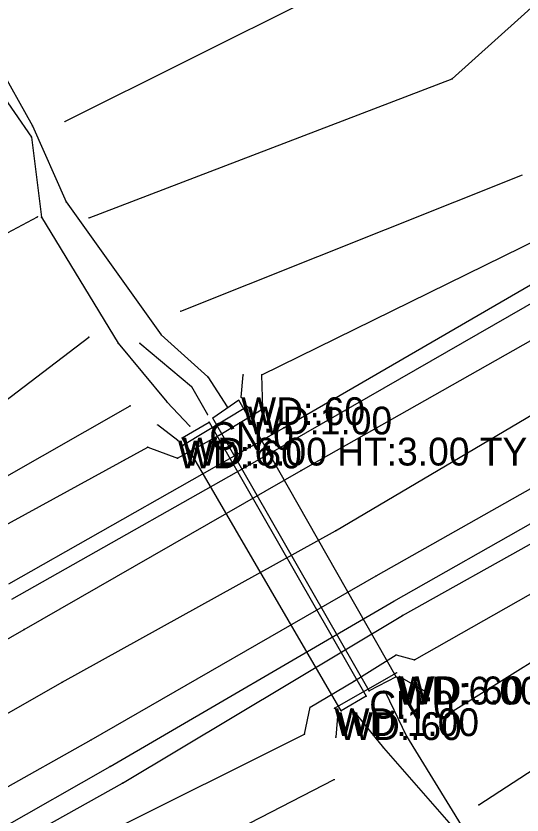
# Model space of a CAD drawing. Extents: x 1419505 to 1434054, y 1956910 to 1968644.
# Drawn here: x 1420049.5 to 1420140.6, y 1957211.1 to 1957354.8 of the extents above; entities that cross this region are included whole.
import ezdxf

# ---------------------------------------------------------------- set-up
doc = ezdxf.new("R2010")
doc.units = 0
for name, color, linetype in [('S_BREAKLINE', 7, 'Continuous'), ('S_CROSS_DRAIN', 7, 'Continuous'), ('S_CROSS_DRAIN_ANNOT', 7, 'Continuous'), ('S_DITCHLINE', 7, 'Continuous'), ('S_DRG_PT_SYM', 7, 'Continuous'), ('S_EDGE_PAVEMENT', 7, 'Continuous'), ('S_GRD_PT_SYM', 7, 'Continuous'), ('S_HEADWALL', 7, 'Continuous'), ('S_HEADWALL_ANNOT', 7, 'Continuous'), ('S_MSC_PT_SYM', 7, 'Continuous'), ('S_PAVEMENT_CROWN', 7, 'Continuous'), ('S_RDW_PT_SYM', 7, 'Continuous'), ('S_SHOULDER', 7, 'Continuous'), ('S_WALL', 7, 'Continuous'), ('S_WALL_ANNOT', 7, 'Continuous')]:
    doc.layers.add(name, color=color, linetype=linetype)

msp = doc.modelspace()

# ---------------------------------------------------------------- linework, layer by layer
at = {"layer": 'S_BREAKLINE'}
for p, q in [((1420127.9904, 1957343.5183), (1420164.2098, 1957376.2314)), ((1420058.3479, 1957335.8728), (1420113.5025, 1957363.3696)), ((1420062.6692, 1957318.5327), (1420127.9904, 1957343.5183)), ((1420079.1623, 1957301.7136), (1420140.6403, 1957326.2372)), ((1420007.4567, 1957294.0961), (1420053.3996, 1957318.7217)), ((1420093.7432, 1957290.3199), (1420146.6607, 1957316.3055)), ((1420097.7205, 1957280.7592), (1420147.7647, 1957309.7911)), ((1420034.2654, 1957275.5089), (1420062.6502, 1957297.0553)), ((1420071.8348, 1957295.9782), (1420081.0834, 1957288.1657)), ((1420093.9612, 1957284.1805), (1420093.7432, 1957290.3199)), ((1420081.0834, 1957288.1657), (1420083.9876, 1957283.1844)), ((1420037.8606, 1957266.3443), (1420070.0887, 1957284.7075)), ((1420086.1067, 1957279.4271), (1420093.9612, 1957284.1805)), ((1420048.2403, 1957252.7354), (1420097.7205, 1957280.7592)), ((1420078.5733, 1957275.3109), (1420086.1067, 1957279.4271)), ((1420042.4399, 1957260.4189), (1420073.2449, 1957277.283)), ((1420073.2449, 1957277.283), (1420078.5733, 1957275.3109)), ((1420121.211, 1957239.0335), (1420187.0263, 1957276.508)), ((1420119.0419, 1957247.0051), (1420167.564, 1957274.1688)), ((1420127.2204, 1957229.2889), (1420189.2894, 1957268.1244)), ((1420132.7968, 1957212.9439), (1420196.5619, 1957254.8196)), ((1420068.6666, 1957216.8621), (1420119.0419, 1957247.0051)), ((1420110.2393, 1957235.1233), (1420117.9418, 1957239.9706)), ((1420117.9418, 1957239.9706), (1420121.211, 1957239.0335)), ((1420102.4758, 1957230.514), (1420110.2393, 1957235.1233)), ((1420101.4407, 1957225.7017), (1420102.4758, 1957230.514)), ((1420063.9153, 1957206.9805), (1420101.4407, 1957225.7017)), ((1420071.8068, 1957199.561), (1420106.7861, 1957217.5232)), ((1420019.4294, 1957189.4423), (1420068.6666, 1957216.8621))]:
    msp.add_line(p, q, dxfattribs=at)
at = {"layer": 'S_CROSS_DRAIN'}
for p, q in [((1420089.64, 1957285.7056), (1420084.9237, 1957282.5193)), ((1420117.9348, 1957236.0053), (1420089.64, 1957285.7056)), ((1420113.0735, 1957233.4652), (1420084.9237, 1957282.5193)), ((1420079.4443, 1957278.9851), (1420084.2976, 1957281.7913)), ((1420084.2976, 1957281.7913), (1420112.5044, 1957232.5051)), ((1420108.0462, 1957229.8769), (1420079.4443, 1957278.9851)), ((1420117.9348, 1957236.0053), (1420113.0735, 1957233.4652)), ((1420112.5044, 1957232.5051), (1420108.0462, 1957229.8769))]:
    msp.add_line(p, q, dxfattribs=at)
at = {"layer": 'S_DITCHLINE'}
for p, q in [((1420042.2079, 1957353.3429), (1420052.5236, 1957335.0637)), ((1420039.4067, 1957351.6418), (1420052.3436, 1957333.0406)), ((1420052.5236, 1957335.0637), (1420058.565, 1957321.3969)), ((1420052.3436, 1957333.0406), (1420054.1217, 1957318.6297)), ((1420058.565, 1957321.3969), (1420075.6421, 1957297.5113)), ((1420054.1217, 1957318.6297), (1420067.9146, 1957295.9772)), ((1420075.6421, 1957297.5113), (1420084.0236, 1957289.9098)), ((1420067.9146, 1957295.9772), (1420076.6621, 1957285.4525)), ((1420084.0236, 1957289.9098), (1420087.5148, 1957284.5545)), ((1420076.6621, 1957285.4525), (1420080.8204, 1957281.0853)), ((1420115.9467, 1957233.2612), (1420119.8009, 1957225.3427)), ((1420109.9293, 1957230.256), (1420115.6606, 1957223.2085)), ((1420119.8009, 1957225.3427), (1420129.6166, 1957209.3256)), ((1420115.6606, 1957223.2085), (1420127.8044, 1957209.3356))]:
    msp.add_line(p, q, dxfattribs=at)
at = {"layer": 'S_DRG_PT_SYM'}
for points in [[(1420089.64, 1957285.7056), (1420089.64, 1957285.7556), (1420089.64, 1957285.7056), (1420089.59, 1957285.7056), (1420089.64, 1957285.7056), (1420089.64, 1957285.6556), (1420089.64, 1957285.7056), (1420089.69, 1957285.7056)], [(1420084.9237, 1957282.5193), (1420084.9237, 1957282.5693), (1420084.9237, 1957282.5193), (1420084.8737, 1957282.5193), (1420084.9237, 1957282.5193), (1420084.9237, 1957282.4693), (1420084.9237, 1957282.5193), (1420084.9737, 1957282.5193)], [(1420084.2976, 1957281.7913), (1420084.2976, 1957281.8413), (1420084.2976, 1957281.7913), (1420084.2476, 1957281.7913), (1420084.2976, 1957281.7913), (1420084.2976, 1957281.7413), (1420084.2976, 1957281.7913), (1420084.3476, 1957281.7913)], [(1420079.4443, 1957278.9851), (1420079.4443, 1957279.0351), (1420079.4443, 1957278.9851), (1420079.3943, 1957278.9851), (1420079.4443, 1957278.9851), (1420079.4443, 1957278.9351), (1420079.4443, 1957278.9851), (1420079.4943, 1957278.9851)], [(1420117.9348, 1957236.0053), (1420117.9348, 1957236.0553), (1420117.9348, 1957236.0053), (1420117.8848, 1957236.0053), (1420117.9348, 1957236.0053), (1420117.9348, 1957235.9553), (1420117.9348, 1957236.0053), (1420117.9848, 1957236.0053)], [(1420113.0735, 1957233.4652), (1420113.0735, 1957233.5152), (1420113.0735, 1957233.4652), (1420113.0235, 1957233.4652), (1420113.0735, 1957233.4652), (1420113.0735, 1957233.4152), (1420113.0735, 1957233.4652), (1420113.1235, 1957233.4652)], [(1420112.5044, 1957232.5051), (1420112.5044, 1957232.5551), (1420112.5044, 1957232.5051), (1420112.4544, 1957232.5051), (1420112.5044, 1957232.5051), (1420112.5044, 1957232.4551), (1420112.5044, 1957232.5051), (1420112.5544, 1957232.5051)], [(1420108.0462, 1957229.8769), (1420108.0462, 1957229.9269), (1420108.0462, 1957229.8769), (1420107.9962, 1957229.8769), (1420108.0462, 1957229.8769), (1420108.0462, 1957229.8269), (1420108.0462, 1957229.8769), (1420108.0962, 1957229.8769)]]:
    msp.add_lwpolyline(points, dxfattribs=at)
at = {"layer": 'S_EDGE_PAVEMENT'}
for p, q in [((1420100.8177, 1957273.1157), (1420152.421, 1957302.3016)), ((1420114.3446, 1957254.1415), (1420163.3257, 1957281.9013)), ((1420051.0225, 1957244.4839), (1420100.8177, 1957273.1157)), ((1420063.0773, 1957224.6846), (1420114.3446, 1957254.1415)), ((1420001.0552, 1957216.0471), (1420051.0225, 1957244.4839)), ((1420013.41, 1957196.7858), (1420063.0773, 1957224.6846))]:
    msp.add_line(p, q, dxfattribs=at)
at = {"layer": 'S_GRD_PT_SYM'}
for points in [[(1420127.9904, 1957343.5183), (1420127.9904, 1957343.5683), (1420127.9904, 1957343.5183), (1420127.9404, 1957343.5183), (1420127.9904, 1957343.5183), (1420127.9904, 1957343.4683), (1420127.9904, 1957343.5183), (1420128.0404, 1957343.5183)], [(1420058.3479, 1957335.8728), (1420058.3479, 1957335.9228), (1420058.3479, 1957335.8728), (1420058.2979, 1957335.8728), (1420058.3479, 1957335.8728), (1420058.3479, 1957335.8228), (1420058.3479, 1957335.8728), (1420058.3979, 1957335.8728)], [(1420052.5236, 1957335.0637), (1420052.5236, 1957335.1137), (1420052.5236, 1957335.0637), (1420052.4736, 1957335.0637), (1420052.5236, 1957335.0637), (1420052.5236, 1957335.0137), (1420052.5236, 1957335.0637), (1420052.5736, 1957335.0637)], [(1420052.3436, 1957333.0406), (1420052.3436, 1957333.0906), (1420052.3436, 1957333.0406), (1420052.2936, 1957333.0406), (1420052.3436, 1957333.0406), (1420052.3436, 1957332.9906), (1420052.3436, 1957333.0406), (1420052.3936, 1957333.0406)], [(1420058.565, 1957321.3969), (1420058.565, 1957321.4469), (1420058.565, 1957321.3969), (1420058.515, 1957321.3969), (1420058.565, 1957321.3969), (1420058.565, 1957321.3469), (1420058.565, 1957321.3969), (1420058.615, 1957321.3969)], [(1420053.3996, 1957318.7217), (1420053.3996, 1957318.7717), (1420053.3996, 1957318.7217), (1420053.3496, 1957318.7217), (1420053.3996, 1957318.7217), (1420053.3996, 1957318.6717), (1420053.3996, 1957318.7217), (1420053.4496, 1957318.7217)], [(1420054.1217, 1957318.6297), (1420054.1217, 1957318.6797), (1420054.1217, 1957318.6297), (1420054.0717, 1957318.6297), (1420054.1217, 1957318.6297), (1420054.1217, 1957318.5797), (1420054.1217, 1957318.6297), (1420054.1717, 1957318.6297)], [(1420062.6692, 1957318.5327), (1420062.6692, 1957318.5827), (1420062.6692, 1957318.5327), (1420062.6192, 1957318.5327), (1420062.6692, 1957318.5327), (1420062.6692, 1957318.4827), (1420062.6692, 1957318.5327), (1420062.7192, 1957318.5327)], [(1420079.1623, 1957301.7136), (1420079.1623, 1957301.7636), (1420079.1623, 1957301.7136), (1420079.1123, 1957301.7136), (1420079.1623, 1957301.7136), (1420079.1623, 1957301.6636), (1420079.1623, 1957301.7136), (1420079.2123, 1957301.7136)], [(1420062.6502, 1957297.0553), (1420062.6502, 1957297.1053), (1420062.6502, 1957297.0553), (1420062.6002, 1957297.0553), (1420062.6502, 1957297.0553), (1420062.6502, 1957297.0053), (1420062.6502, 1957297.0553), (1420062.7002, 1957297.0553)], [(1420075.6421, 1957297.5113), (1420075.6421, 1957297.5613), (1420075.6421, 1957297.5113), (1420075.5921, 1957297.5113), (1420075.6421, 1957297.5113), (1420075.6421, 1957297.4613), (1420075.6421, 1957297.5113), (1420075.6921, 1957297.5113)], [(1420067.9146, 1957295.9772), (1420067.9146, 1957296.0272), (1420067.9146, 1957295.9772), (1420067.8646, 1957295.9772), (1420067.9146, 1957295.9772), (1420067.9146, 1957295.9272), (1420067.9146, 1957295.9772), (1420067.9646, 1957295.9772)], [(1420071.8348, 1957295.9782), (1420071.8348, 1957296.0282), (1420071.8348, 1957295.9782), (1420071.7848, 1957295.9782), (1420071.8348, 1957295.9782), (1420071.8348, 1957295.9282), (1420071.8348, 1957295.9782), (1420071.8848, 1957295.9782)], [(1420084.0236, 1957289.9098), (1420084.0236, 1957289.9598), (1420084.0236, 1957289.9098), (1420083.9736, 1957289.9098), (1420084.0236, 1957289.9098), (1420084.0236, 1957289.8598), (1420084.0236, 1957289.9098), (1420084.0736, 1957289.9098)], [(1420093.7432, 1957290.3199), (1420093.7432, 1957290.3699), (1420093.7432, 1957290.3199), (1420093.6932, 1957290.3199), (1420093.7432, 1957290.3199), (1420093.7432, 1957290.2699), (1420093.7432, 1957290.3199), (1420093.7932, 1957290.3199)], [(1420081.0834, 1957288.1657), (1420081.0834, 1957288.2157), (1420081.0834, 1957288.1657), (1420081.0334, 1957288.1657), (1420081.0834, 1957288.1657), (1420081.0834, 1957288.1157), (1420081.0834, 1957288.1657), (1420081.1334, 1957288.1657)], [(1420076.6621, 1957285.4525), (1420076.6621, 1957285.5025), (1420076.6621, 1957285.4525), (1420076.6121, 1957285.4525), (1420076.6621, 1957285.4525), (1420076.6621, 1957285.4025), (1420076.6621, 1957285.4525), (1420076.7121, 1957285.4525)], [(1420070.0887, 1957284.7075), (1420070.0887, 1957284.7575), (1420070.0887, 1957284.7075), (1420070.0387, 1957284.7075), (1420070.0887, 1957284.7075), (1420070.0887, 1957284.6575), (1420070.0887, 1957284.7075), (1420070.1387, 1957284.7075)], [(1420087.5148, 1957284.5545), (1420087.5148, 1957284.6045), (1420087.5148, 1957284.5545), (1420087.4648, 1957284.5545), (1420087.5148, 1957284.5545), (1420087.5148, 1957284.5045), (1420087.5148, 1957284.5545), (1420087.5648, 1957284.5545)], [(1420093.9612, 1957284.1805), (1420093.9612, 1957284.2305), (1420093.9612, 1957284.1805), (1420093.9112, 1957284.1805), (1420093.9612, 1957284.1805), (1420093.9612, 1957284.1305), (1420093.9612, 1957284.1805), (1420094.0112, 1957284.1805)], [(1420083.9876, 1957283.1844), (1420083.9876, 1957283.2344), (1420083.9876, 1957283.1844), (1420083.9376, 1957283.1844), (1420083.9876, 1957283.1844), (1420083.9876, 1957283.1344), (1420083.9876, 1957283.1844), (1420084.0376, 1957283.1844)], [(1420080.8204, 1957281.0853), (1420080.8204, 1957281.1353), (1420080.8204, 1957281.0853), (1420080.7704, 1957281.0853), (1420080.8204, 1957281.0853), (1420080.8204, 1957281.0353), (1420080.8204, 1957281.0853), (1420080.8704, 1957281.0853)], [(1420097.7205, 1957280.7592), (1420097.7205, 1957280.8092), (1420097.7205, 1957280.7592), (1420097.6705, 1957280.7592), (1420097.7205, 1957280.7592), (1420097.7205, 1957280.7092), (1420097.7205, 1957280.7592), (1420097.7705, 1957280.7592)], [(1420086.1067, 1957279.4271), (1420086.1067, 1957279.4771), (1420086.1067, 1957279.4271), (1420086.0567, 1957279.4271), (1420086.1067, 1957279.4271), (1420086.1067, 1957279.3771), (1420086.1067, 1957279.4271), (1420086.1567, 1957279.4271)], [(1420073.2449, 1957277.283), (1420073.2449, 1957277.333), (1420073.2449, 1957277.283), (1420073.1949, 1957277.283), (1420073.2449, 1957277.283), (1420073.2449, 1957277.233), (1420073.2449, 1957277.283), (1420073.2949, 1957277.283)], [(1420078.5733, 1957275.3109), (1420078.5733, 1957275.3609), (1420078.5733, 1957275.3109), (1420078.5233, 1957275.3109), (1420078.5733, 1957275.3109), (1420078.5733, 1957275.2609), (1420078.5733, 1957275.3109), (1420078.6233, 1957275.3109)], [(1420119.0419, 1957247.0051), (1420119.0419, 1957247.0551), (1420119.0419, 1957247.0051), (1420118.9919, 1957247.0051), (1420119.0419, 1957247.0051), (1420119.0419, 1957246.9551), (1420119.0419, 1957247.0051), (1420119.0919, 1957247.0051)], [(1420117.9418, 1957239.9706), (1420117.9418, 1957240.0206), (1420117.9418, 1957239.9706), (1420117.8918, 1957239.9706), (1420117.9418, 1957239.9706), (1420117.9418, 1957239.9206), (1420117.9418, 1957239.9706), (1420117.9918, 1957239.9706)], [(1420121.211, 1957239.0335), (1420121.211, 1957239.0835), (1420121.211, 1957239.0335), (1420121.161, 1957239.0335), (1420121.211, 1957239.0335), (1420121.211, 1957238.9835), (1420121.211, 1957239.0335), (1420121.261, 1957239.0335)], [(1420110.2393, 1957235.1233), (1420110.2393, 1957235.1733), (1420110.2393, 1957235.1233), (1420110.1893, 1957235.1233), (1420110.2393, 1957235.1233), (1420110.2393, 1957235.0733), (1420110.2393, 1957235.1233), (1420110.2893, 1957235.1233)], [(1420115.9467, 1957233.2612), (1420115.9467, 1957233.3112), (1420115.9467, 1957233.2612), (1420115.8967, 1957233.2612), (1420115.9467, 1957233.2612), (1420115.9467, 1957233.2112), (1420115.9467, 1957233.2612), (1420115.9967, 1957233.2612)], [(1420102.4758, 1957230.514), (1420102.4758, 1957230.564), (1420102.4758, 1957230.514), (1420102.4258, 1957230.514), (1420102.4758, 1957230.514), (1420102.4758, 1957230.464), (1420102.4758, 1957230.514), (1420102.5258, 1957230.514)], [(1420109.9293, 1957230.256), (1420109.9293, 1957230.306), (1420109.9293, 1957230.256), (1420109.8793, 1957230.256), (1420109.9293, 1957230.256), (1420109.9293, 1957230.206), (1420109.9293, 1957230.256), (1420109.9793, 1957230.256)], [(1420127.2204, 1957229.2889), (1420127.2204, 1957229.3389), (1420127.2204, 1957229.2889), (1420127.1704, 1957229.2889), (1420127.2204, 1957229.2889), (1420127.2204, 1957229.2389), (1420127.2204, 1957229.2889), (1420127.2704, 1957229.2889)], [(1420101.4407, 1957225.7017), (1420101.4407, 1957225.7517), (1420101.4407, 1957225.7017), (1420101.3907, 1957225.7017), (1420101.4407, 1957225.7017), (1420101.4407, 1957225.6517), (1420101.4407, 1957225.7017), (1420101.4907, 1957225.7017)], [(1420119.8009, 1957225.3427), (1420119.8009, 1957225.3927), (1420119.8009, 1957225.3427), (1420119.7509, 1957225.3427), (1420119.8009, 1957225.3427), (1420119.8009, 1957225.2927), (1420119.8009, 1957225.3427), (1420119.8509, 1957225.3427)], [(1420115.6606, 1957223.2085), (1420115.6606, 1957223.2585), (1420115.6606, 1957223.2085), (1420115.6106, 1957223.2085), (1420115.6606, 1957223.2085), (1420115.6606, 1957223.1585), (1420115.6606, 1957223.2085), (1420115.7106, 1957223.2085)], [(1420106.7861, 1957217.5232), (1420106.7861, 1957217.5732), (1420106.7861, 1957217.5232), (1420106.7361, 1957217.5232), (1420106.7861, 1957217.5232), (1420106.7861, 1957217.4732), (1420106.7861, 1957217.5232), (1420106.8361, 1957217.5232)], [(1420068.6666, 1957216.8621), (1420068.6666, 1957216.9121), (1420068.6666, 1957216.8621), (1420068.6166, 1957216.8621), (1420068.6666, 1957216.8621), (1420068.6666, 1957216.8121), (1420068.6666, 1957216.8621), (1420068.7166, 1957216.8621)], [(1420132.7968, 1957212.9439), (1420132.7968, 1957212.9939), (1420132.7968, 1957212.9439), (1420132.7468, 1957212.9439), (1420132.7968, 1957212.9439), (1420132.7968, 1957212.8939), (1420132.7968, 1957212.9439), (1420132.8468, 1957212.9439)]]:
    msp.add_lwpolyline(points, dxfattribs=at)
at = {"layer": 'S_HEADWALL'}
for p, q in [((1420091.1791, 1957284.5715), (1420079.5663, 1957277.582)), ((1420106.8121, 1957230.326), (1420117.9478, 1957236.6944))]:
    msp.add_line(p, q, dxfattribs=at)
at = {"layer": 'S_MSC_PT_SYM'}
for points in [[(1420090.401, 1957290.3079), (1420090.401, 1957290.3579), (1420090.401, 1957290.3079), (1420090.351, 1957290.3079), (1420090.401, 1957290.3079), (1420090.401, 1957290.2579), (1420090.401, 1957290.3079), (1420090.451, 1957290.3079)], [(1420090.023, 1957286.2466), (1420090.023, 1957286.2966), (1420090.023, 1957286.2466), (1420089.973, 1957286.2466), (1420090.023, 1957286.2466), (1420090.023, 1957286.1966), (1420090.023, 1957286.2466), (1420090.073, 1957286.2466)], [(1420091.1791, 1957284.5715), (1420091.1791, 1957284.6215), (1420091.1791, 1957284.5715), (1420091.1291, 1957284.5715), (1420091.1791, 1957284.5715), (1420091.1791, 1957284.5215), (1420091.1791, 1957284.5715), (1420091.2291, 1957284.5715)], [(1420075.013, 1957281.2703), (1420075.013, 1957281.3203), (1420075.013, 1957281.2703), (1420074.963, 1957281.2703), (1420075.013, 1957281.2703), (1420075.013, 1957281.2203), (1420075.013, 1957281.2703), (1420075.063, 1957281.2703)], [(1420078.6433, 1957278.4701), (1420078.6433, 1957278.5201), (1420078.6433, 1957278.4701), (1420078.5933, 1957278.4701), (1420078.6433, 1957278.4701), (1420078.6433, 1957278.4201), (1420078.6433, 1957278.4701), (1420078.6933, 1957278.4701)], [(1420079.5663, 1957277.582), (1420079.5663, 1957277.632), (1420079.5663, 1957277.582), (1420079.5163, 1957277.582), (1420079.5663, 1957277.582), (1420079.5663, 1957277.532), (1420079.5663, 1957277.582), (1420079.6163, 1957277.582)], [(1420117.9478, 1957236.6944), (1420117.9478, 1957236.7444), (1420117.9478, 1957236.6944), (1420117.8978, 1957236.6944), (1420117.9478, 1957236.6944), (1420117.9478, 1957236.6444), (1420117.9478, 1957236.6944), (1420117.9978, 1957236.6944)], [(1420118.4878, 1957236.0563), (1420118.4878, 1957236.1063), (1420118.4878, 1957236.0563), (1420118.4378, 1957236.0563), (1420118.4878, 1957236.0563), (1420118.4878, 1957236.0063), (1420118.4878, 1957236.0563), (1420118.5378, 1957236.0563)], [(1420123.1781, 1957233.3692), (1420123.1781, 1957233.4192), (1420123.1781, 1957233.3692), (1420123.1281, 1957233.3692), (1420123.1781, 1957233.3692), (1420123.1781, 1957233.3192), (1420123.1781, 1957233.3692), (1420123.2281, 1957233.3692)], [(1420106.8121, 1957230.326), (1420106.8121, 1957230.376), (1420106.8121, 1957230.326), (1420106.7621, 1957230.326), (1420106.8121, 1957230.326), (1420106.8121, 1957230.276), (1420106.8121, 1957230.326), (1420106.8621, 1957230.326)], [(1420107.4281, 1957229.6249), (1420107.4281, 1957229.6749), (1420107.4281, 1957229.6249), (1420107.3781, 1957229.6249), (1420107.4281, 1957229.6249), (1420107.4281, 1957229.5749), (1420107.4281, 1957229.6249), (1420107.4781, 1957229.6249)], [(1420107.0611, 1957225.1236), (1420107.0611, 1957225.1736), (1420107.0611, 1957225.1236), (1420107.0111, 1957225.1236), (1420107.0611, 1957225.1236), (1420107.0611, 1957225.0736), (1420107.0611, 1957225.1236), (1420107.1111, 1957225.1236)]]:
    msp.add_lwpolyline(points, dxfattribs=at)
at = {"layer": 'S_PAVEMENT_CROWN'}
for p, q in [((1420106.9871, 1957262.218), (1420158.0084, 1957292.361)), ((1420057.8519, 1957235.0013), (1420106.9871, 1957262.218)), ((1420007.0106, 1957206.0824), (1420057.8519, 1957235.0013))]:
    msp.add_line(p, q, dxfattribs=at)
at = {"layer": 'S_RDW_PT_SYM'}
for points in [[(1420098.8566, 1957278.2571), (1420098.8566, 1957278.3071), (1420098.8566, 1957278.2571), (1420098.8066, 1957278.2571), (1420098.8566, 1957278.2571), (1420098.8566, 1957278.2071), (1420098.8566, 1957278.2571), (1420098.9066, 1957278.2571)], [(1420100.8177, 1957273.1157), (1420100.8177, 1957273.1657), (1420100.8177, 1957273.1157), (1420100.7677, 1957273.1157), (1420100.8177, 1957273.1157), (1420100.8177, 1957273.0657), (1420100.8177, 1957273.1157), (1420100.8677, 1957273.1157)], [(1420106.9871, 1957262.218), (1420106.9871, 1957262.268), (1420106.9871, 1957262.218), (1420106.9371, 1957262.218), (1420106.9871, 1957262.218), (1420106.9871, 1957262.168), (1420106.9871, 1957262.218), (1420107.0371, 1957262.218)], [(1420114.3446, 1957254.1415), (1420114.3446, 1957254.1915), (1420114.3446, 1957254.1415), (1420114.2946, 1957254.1415), (1420114.3446, 1957254.1415), (1420114.3446, 1957254.0915), (1420114.3446, 1957254.1415), (1420114.3946, 1957254.1415)], [(1420117.5178, 1957249.6112), (1420117.5178, 1957249.6612), (1420117.5178, 1957249.6112), (1420117.4678, 1957249.6112), (1420117.5178, 1957249.6112), (1420117.5178, 1957249.5612), (1420117.5178, 1957249.6112), (1420117.5678, 1957249.6112)], [(1420051.0225, 1957244.4839), (1420051.0225, 1957244.5339), (1420051.0225, 1957244.4839), (1420050.9725, 1957244.4839), (1420051.0225, 1957244.4839), (1420051.0225, 1957244.4339), (1420051.0225, 1957244.4839), (1420051.0725, 1957244.4839)], [(1420057.8519, 1957235.0013), (1420057.8519, 1957235.0513), (1420057.8519, 1957235.0013), (1420057.8019, 1957235.0013), (1420057.8519, 1957235.0013), (1420057.8519, 1957234.9513), (1420057.8519, 1957235.0013), (1420057.9019, 1957235.0013)], [(1420063.0773, 1957224.6846), (1420063.0773, 1957224.7346), (1420063.0773, 1957224.6846), (1420063.0273, 1957224.6846), (1420063.0773, 1957224.6846), (1420063.0773, 1957224.6346), (1420063.0773, 1957224.6846), (1420063.1273, 1957224.6846)], [(1420066.4545, 1957219.8703), (1420066.4545, 1957219.9203), (1420066.4545, 1957219.8703), (1420066.4045, 1957219.8703), (1420066.4545, 1957219.8703), (1420066.4545, 1957219.8203), (1420066.4545, 1957219.8703), (1420066.5045, 1957219.8703)]]:
    msp.add_lwpolyline(points, dxfattribs=at)
at = {"layer": 'S_SHOULDER'}
for p, q in [((1420098.8566, 1957278.2571), (1420149.2958, 1957307.2149)), ((1420048.7923, 1957249.9312), (1420098.8566, 1957278.2571)), ((1420117.5178, 1957249.6112), (1420165.9929, 1957277.118)), ((1420066.4545, 1957219.8703), (1420117.5178, 1957249.6112)), ((1420017.1663, 1957191.9195), (1420066.4545, 1957219.8703))]:
    msp.add_line(p, q, dxfattribs=at)
at = {"layer": 'S_WALL'}
for p, q in [((1420090.023, 1957286.2466), (1420090.401, 1957290.3079)), ((1420078.6433, 1957278.4701), (1420075.013, 1957281.2703)), ((1420118.4878, 1957236.0563), (1420123.1781, 1957233.3692)), ((1420107.4281, 1957229.6249), (1420107.0611, 1957225.1236))]:
    msp.add_line(p, q, dxfattribs=at)

# ---------------------------------------------------------------- texts
at = {"layer": 'S_CROSS_DRAIN_ANNOT'}
for s, p in [('CN:0', (1420084.2976, 1957276.7913)), ('WD:6.00 HT:3.00 TY:RC BOX CN:0', (1420079.4443, 1957273.9851)), ('WD:6.00 HT:3.00 TY:RC BOX CN:0', (1420117.9348, 1957231.0053)), ('CN:0', (1420113.0735, 1957228.4652))]:
    msp.add_text(s, height=5, dxfattribs=at).set_placement(p)
at = {"layer": 'S_HEADWALL_ANNOT'}
for p in [(1420091.1791, 1957279.5715), (1420106.8121, 1957225.326)]:
    msp.add_text('WD:1.00', height=5, dxfattribs=at).set_placement(p)
at = {"layer": 'S_WALL_ANNOT'}
for p in [(1420090.023, 1957281.2466), (1420078.6433, 1957273.4701), (1420118.4878, 1957231.0563), (1420107.4281, 1957224.6249)]:
    msp.add_text('WD:.60', height=5, dxfattribs=at).set_placement(p)

doc.saveas('drawing.dxf')
